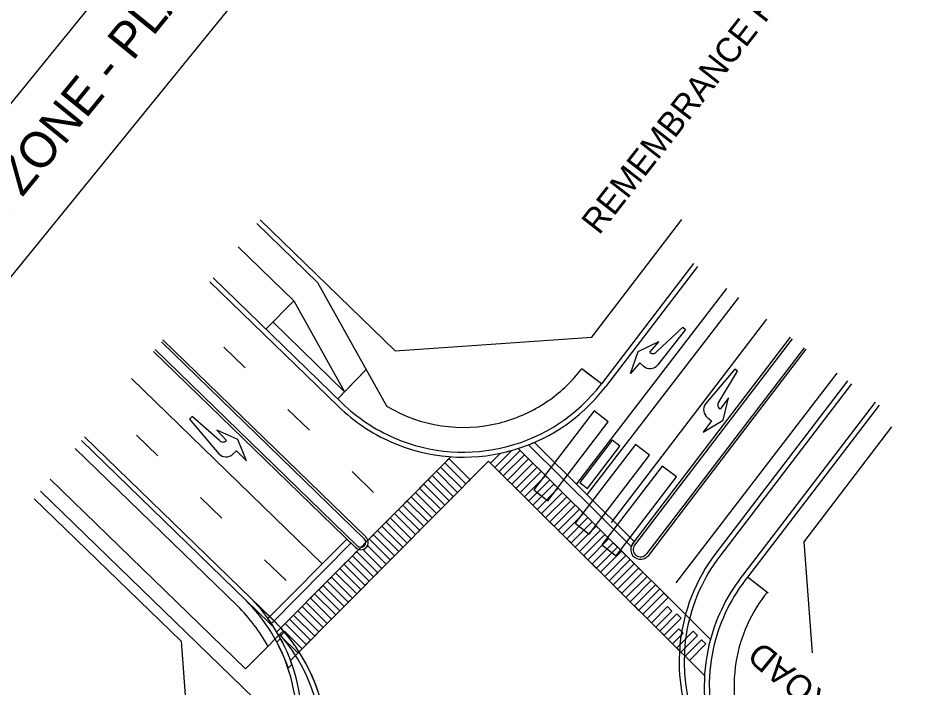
# Model space of a CAD drawing. Extents: x 592613 to 600223, y 4837996 to 4840103.
# Drawn here: x 592951.62 to 592974.48, y 4839245.35 to 4839262.21 of the extents above; entities that cross this region are included whole.
import ezdxf

# ---------------------------------------------------------------- set-up
doc = ezdxf.new("R2010")
doc.units = 0
for name, color, linetype in [('ENG_BUS-PAD', 7, 'Continuous'), ('ENG_CURB-BACK', 7, 'Continuous'), ('ENG_CURBSTOP', 7, 'Continuous'), ('ENG_EPAVT', 7, 'Continuous'), ('ENG_KILLSTRIP', 7, 'Continuous'), ('ENG_LANEWAY', 7, 'Continuous'), ('ENG_MULTI-TRAIL', 7, 'Continuous'), ('ENG_SIDEWALK', 7, 'Continuous'), ('ENG_TITLEBLOCK', 7, 'Continuous'), ('ENG_TX_TITLEBLOCK', 7, 'Continuous'), ('Level 11', 7, 'Continuous'), ('Level 12', 7, 'Continuous'), ('Level 32', 7, 'Continuous'), ('Level 33', 7, 'Continuous'), ('PMK_LANE', 7, 'Continuous'), ('PMK_LANE_3-6', 7, 'Continuous'), ('ROW_ENG_ROW', 7, 'Continuous'), ('ROW_ENG_ROW BO', 7, 'Continuous')]:
    doc.layers.add(name, color=color, linetype=linetype)

msp = doc.modelspace()

# ---------------------------------------------------------------- linework, layer by layer
at = {"layer": 'ENG_BUS-PAD'}
for p, q in [((592958.554, 4839255.093), (592957.155, 4839256.453)), ((592957.85, 4839254.383), (592958.554, 4839255.093))]:
    msp.add_line(p, q, dxfattribs=at)
at = {"layer": 'ENG_CURB-BACK'}
for p, q in [((592968.611, 4839256.033), (592966.296, 4839253.001)), ((592959.77, 4839252.518), (592956.523, 4839255.672)), ((592971.095, 4839254.137), (592968.15, 4839250.279)), ((592960.327, 4839249.101), (592955.222, 4839254.061)), ((592960.153, 4839248.921), (592955.064, 4839253.866)), ((592972.585, 4839252.999), (592969.274, 4839248.661)), ((592973.281, 4839252.468), (592969.969, 4839248.13)), ((592957.943, 4839246.973), (592953.21, 4839251.571)), ((592969.969, 4839248.13), (592969.906, 4839248.047))]:
    msp.add_line(p, q, dxfattribs=at)
for centre, radius, start, end in [((592962.819, 4839255.656), 4.375, 246.6005, 322.6377), ((592962.819, 4839255.656), 4.375, 225.8289, 246.6005), ((592960.24, 4839249.011), 0.125, 315.8289, 45.8289), ((592960.24, 4839249.011), 0.125, 225.8289, 315.8289), ((592972.751, 4839246.006), 4.375, 142.6377, 169.6205), ((592973.383, 4839245.392), 4.375, 142.6377, 167.7306), ((592954.262, 4839244.449), 4.375, 27.9119, 45.8289), ((592954.262, 4839244.449), 4.125, 28.0452, 45.829), ((592954.894, 4839243.835), 4.375, 44.5335, 45.8289), ((592954.894, 4839243.835), 4.375, 348.3699, 40.8056), ((592972.751, 4839246.006), 4.375, 169.6205, 225.8289), ((592954.262, 4839244.449), 4.375, 322.6377, 27.9119), ((592973.383, 4839245.392), 4.375, 167.7306, 225.8289)]:
    msp.add_arc(centre, radius, start, end, dxfattribs=at)
at = {"layer": 'ENG_CURBSTOP'}
msp.add_lwpolyline([(592958.411, 4839245.837), (592958.509, 4839245.936), (592958.443, 4839246.113), (592958.386, 4839246.249), (592958.331, 4839246.371), (592958.25, 4839246.534), (592958.222, 4839246.588), (592958.222, 4839246.588), (592958.131, 4839246.496), (592958.164, 4839246.417), (592958.283, 4839246.173), (592958.368, 4839245.959)], close=True, dxfattribs=at)
at = {"layer": 'ENG_EPAVT'}
for p, q in [((592968.711, 4839255.957), (592966.395, 4839252.925)), ((592959.683, 4839252.428), (592956.444, 4839255.574)), ((592971.045, 4839254.175), (592968.112, 4839250.333)), ((592960.371, 4839249.146), (592955.261, 4839254.11)), ((592971.393, 4839253.909), (592968.367, 4839249.946)), ((592960.11, 4839248.877), (592955.024, 4839253.817)), ((592971.443, 4839253.871), (592968.406, 4839249.894)), ((592972.486, 4839253.075), (592969.174, 4839248.737)), ((592973.182, 4839252.544), (592969.87, 4839248.206)), ((592958.03, 4839247.063), (592953.289, 4839251.669)), ((592957.341, 4839245.827), (592952.423, 4839250.598)), ((592968.112, 4839250.333), (592967.086, 4839248.989)), ((592968.149, 4839250.278), (592967.128, 4839248.941)), ((592968.367, 4839249.946), (592967.43, 4839248.719)), ((592968.405, 4839249.893), (592967.48, 4839248.681)), ((592969.87, 4839248.206), (592969.806, 4839248.123)), ((592957.589, 4839246.077), (592957.968, 4839246.456)), ((592957.341, 4839245.827), (592957.589, 4839246.077))]:
    msp.add_line(p, q, dxfattribs=at)
for centre, radius, start, end in [((592962.819, 4839255.656), 4.5, 246.1583, 322.6377), ((592962.819, 4839255.656), 4.5, 225.8289, 246.1583), ((592960.24, 4839249.011), 0.188, 315.8289, 45.8289), ((592960.24, 4839249.011), 0.188, 225.8289, 315.8289), ((592967.281, 4839248.832), 0.25, 141.1016, 322.9443), ((592967.281, 4839248.832), 0.187, 144.4115, 322.9443), ((592972.751, 4839246.006), 4.5, 142.6377, 174.56), ((592973.383, 4839245.392), 4.5, 142.6377, 166.783), ((592954.262, 4839244.449), 4.5, 33.0068, 45.8289), ((592954.894, 4839243.835), 4.5, 322.6377, 51.4479), ((592954.894, 4839243.835), 4.5, 349.35, 45.8289), ((592954.262, 4839244.449), 4.5, 343.3725, 33.0068), ((592972.751, 4839246.006), 4.5, 170.2582, 184.2333), ((592973.383, 4839245.392), 4.5, 166.783, 225.8289), ((592972.751, 4839246.006), 4.5, 184.2333, 225.8289)]:
    msp.add_arc(centre, radius, start, end, dxfattribs=at)
at = {"layer": 'ENG_KILLSTRIP'}
for p, q in [((592959.834, 4839252.804), (592958.026, 4839254.561)), ((592957.136, 4839247.408), (592953.052, 4839251.376))]:
    msp.add_line(p, q, dxfattribs=at)
at = {"layer": 'ENG_LANEWAY'}
for p, q in [((592969.444, 4839255.403), (592965.665, 4839250.481)), ((592969.741, 4839255.174), (592965.938, 4839250.22)), ((592972.22, 4839253.271), (592968.168, 4839247.993))]:
    msp.add_line(p, q, dxfattribs=at)
at = {"layer": 'ENG_MULTI-TRAIL'}
for p, q in [((592959.155, 4839255.555), (592957.628, 4839257.039)), ((592958.554, 4839255.093), (592959.834, 4839252.804))]:
    msp.add_line(p, q, dxfattribs=at)
at = {"layer": 'ENG_SIDEWALK'}
for p, q in [((592959.155, 4839255.555), (592960.9, 4839252.433)), ((592960.379, 4839253.366), (592959.659, 4839252.625)), ((592959.834, 4839252.804), (592960.379, 4839253.366)), ((592966.296, 4839253.001), (592965.799, 4839253.38)), ((592966.296, 4839253.001), (592965.899, 4839253.304)), ((592959.661, 4839252.623), (592959.834, 4839252.804)), ((592958.007, 4839244.645), (592952.184, 4839250.302)), ((592970.495, 4839247.729), (592969.969, 4839248.13)), ((592970.367, 4839247.827), (592969.969, 4839248.13)), ((592970.403, 4839247.668), (592970.466, 4839247.751)), ((592957.812, 4839246.298), (592958.196, 4839246.685)), ((592958.196, 4839246.685), (592958.303, 4839246.792))]:
    msp.add_line(p, q, dxfattribs=at)
for centre, start, end in [((592962.819, 4839255.656), 305.4959, 322.6377), ((592962.819, 4839255.656), 302.8741, 305.4959), ((592962.819, 4839255.656), 239.233, 283.8878), ((592962.819, 4839255.656), 283.8878, 302.8741), ((592973.383, 4839245.392), 142.6377, 172.7872), ((592973.383, 4839245.392), 172.7872, 204.683)]:
    msp.add_arc(centre, 3.75, start, end, dxfattribs=at)
at = {"layer": 'ENG_TITLEBLOCK'}
msp.add_line((592939.353, 4839240.83), (592966.893, 4839274.724), dxfattribs=at)
msp.add_line((592939.353, 4839240.83), (592966.893, 4839274.724), dxfattribs=at)
msp.add_lwpolyline([(592937.219, 4839242.565), (592964.758, 4839276.458)], dxfattribs=at)
msp.add_lwpolyline([(592937.219, 4839242.565), (592964.758, 4839276.458)], dxfattribs=at)
at = {"layer": 'Level 11'}
for p, q in [((592966.112, 4839252.318), (592964.593, 4839250.332)), ((592966.469, 4839252.045), (592966.112, 4839252.318)), ((592964.95, 4839250.059), (592966.469, 4839252.045)), ((592967.151, 4839251.478), (592965.632, 4839249.493)), ((592966.566, 4839251.58), (592965.753, 4839250.516)), ((592965.944, 4839250.37), (592966.758, 4839251.433)), ((592966.758, 4839251.433), (592966.566, 4839251.58)), ((592967.508, 4839251.205), (592967.151, 4839251.478)), ((592965.989, 4839249.219), (592967.508, 4839251.205)), ((592967.826, 4839250.932), (592966.308, 4839248.947)), ((592968.184, 4839250.659), (592967.826, 4839250.932)), ((592965.753, 4839250.516), (592965.944, 4839250.37)), ((592966.665, 4839248.673), (592968.184, 4839250.659)), ((592964.593, 4839250.332), (592964.95, 4839250.059)), ((592965.632, 4839249.493), (592965.989, 4839249.219)), ((592966.308, 4839248.947), (592966.665, 4839248.673))]:
    msp.add_line(p, q, dxfattribs=at)
at = {"layer": 'Level 12'}
for p, q in [((592967.685, 4839253.805), (592968.346, 4839254.433)), ((592968.415, 4839254.372), (592967.709, 4839253.47)), ((592968.346, 4839254.433), (592968.415, 4839254.372)), ((592967.216, 4839253.815), (592967.741, 4839254.067)), ((592967.741, 4839254.067), (592967.503, 4839253.8)), ((592967.025, 4839253.265), (592967.216, 4839253.815)), ((592967.264, 4839253.532), (592967.025, 4839253.265)), ((592967.356, 4839253.45), (592967.264, 4839253.532)), ((592969.649, 4839253.375), (592968.914, 4839252.496)), ((592969.247, 4839252.542), (592969.722, 4839253.321)), ((592969.722, 4839253.321), (592969.649, 4839253.375)), ((592969.491, 4839252.653), (592969.28, 4839252.363)), ((592969.355, 4839252.086), (592969.491, 4839252.653)), ((592955.998, 4839252.179), (592955.932, 4839252.116)), ((592955.932, 4839252.116), (592956.67, 4839251.239)), ((592956.682, 4839251.575), (592955.998, 4839252.179)), ((592968.857, 4839251.784), (592969.355, 4839252.086)), ((592969.069, 4839252.074), (592968.857, 4839251.784)), ((592968.969, 4839252.147), (592969.069, 4839252.074)), ((592957.15, 4839251.603), (592956.616, 4839251.835)), ((592956.616, 4839251.835), (592956.864, 4839251.576)), ((592957.361, 4839251.059), (592957.15, 4839251.603)), ((592957.023, 4839251.232), (592957.113, 4839251.318)), ((592957.113, 4839251.318), (592957.361, 4839251.059))]:
    msp.add_line(p, q, dxfattribs=at)
for centre, radius, start, end in [((592967.591, 4839253.888), 0.125, 228.2469, 318.2706), ((592967.523, 4839253.636), 0.25, 228.242, 318.2642), ((592969.348, 4839252.469), 0.125, 143.8443, 233.8679), ((592969.116, 4839252.349), 0.25, 143.8506, 233.8728), ((592956.772, 4839251.662), 0.125, 223.8199, 313.8436), ((592956.85, 4839251.412), 0.25, 223.8262, 313.8484)]:
    msp.add_arc(centre, radius, start, end, dxfattribs=at)
at = {"layer": 'PMK_LANE'}
for p, q in [((592970.449, 4839254.63), (592966.539, 4839249.508)), ((592959.27, 4839248.472), (592954.472, 4839253.133)), ((592964.461, 4839251.466), (592967.041, 4839248.903)), ((592964.611, 4839251.528), (592967.121, 4839249.035)), ((592962.508, 4839251.166), (592958.128, 4839246.753)), ((592963.758, 4839251.255), (592963.508, 4839251.003)), ((592963.614, 4839250.897), (592964.039, 4839251.324)), ((592964.25, 4839251.323), (592963.721, 4839250.792)), ((592963.827, 4839250.686), (592964.356, 4839251.218)), ((592964.2, 4839251.373), (592968.041, 4839247.558)), ((592964.356, 4839251.218), (592964.25, 4839251.323)), ((592963.455, 4839251.056), (592958.473, 4839246.037)), ((592962.46, 4839251.118), (592962.355, 4839251.012)), ((592962.355, 4839251.012), (592962.885, 4839250.482)), ((592962.991, 4839250.588), (592962.46, 4839251.118)), ((592963.455, 4839251.056), (592968.891, 4839245.656)), ((592963.508, 4839251.003), (592963.614, 4839250.897)), ((592964.463, 4839251.112), (592963.934, 4839250.58)), ((592964.04, 4839250.475), (592964.569, 4839251.006)), ((592964.569, 4839251.006), (592964.463, 4839251.112)), ((592962.038, 4839250.692), (592961.932, 4839250.586)), ((592962.568, 4839250.162), (592962.038, 4839250.692)), ((592962.249, 4839250.905), (592962.143, 4839250.799)), ((592962.143, 4839250.799), (592962.674, 4839250.269)), ((592962.78, 4839250.375), (592962.249, 4839250.905)), ((592963.721, 4839250.792), (592963.827, 4839250.686)), ((592964.676, 4839250.9), (592964.146, 4839250.369)), ((592964.253, 4839250.263), (592964.782, 4839250.795)), ((592964.782, 4839250.795), (592964.676, 4839250.9)), ((592961.826, 4839250.479), (592961.72, 4839250.373)), ((592962.357, 4839249.949), (592961.826, 4839250.479)), ((592961.932, 4839250.586), (592962.463, 4839250.056)), ((592962.885, 4839250.482), (592962.991, 4839250.588)), ((592963.934, 4839250.58), (592964.04, 4839250.475)), ((592964.888, 4839250.689), (592964.359, 4839250.157)), ((592964.466, 4839250.052), (592964.995, 4839250.583)), ((592965.101, 4839250.478), (592964.572, 4839249.946)), ((592964.995, 4839250.583), (592964.888, 4839250.689)), ((592965.208, 4839250.372), (592965.101, 4839250.478)), ((592961.615, 4839250.266), (592961.509, 4839250.16)), ((592962.146, 4839249.737), (592961.615, 4839250.266)), ((592961.72, 4839250.373), (592962.251, 4839249.843)), ((592962.674, 4839250.269), (592962.78, 4839250.375)), ((592964.146, 4839250.369), (592964.253, 4839250.263)), ((592964.679, 4839249.84), (592965.208, 4839250.372)), ((592965.314, 4839250.266), (592964.785, 4839249.735)), ((592965.421, 4839250.16), (592965.314, 4839250.266)), ((592961.403, 4839250.054), (592961.298, 4839249.947)), ((592961.934, 4839249.524), (592961.403, 4839250.054)), ((592961.509, 4839250.16), (592962.04, 4839249.63)), ((592962.463, 4839250.056), (592962.568, 4839250.162)), ((592964.359, 4839250.157), (592964.466, 4839250.052)), ((592964.891, 4839249.629), (592965.421, 4839250.16)), ((592965.527, 4839250.055), (592964.998, 4839249.523)), ((592965.633, 4839249.949), (592965.527, 4839250.055)), ((592961.723, 4839249.311), (592961.192, 4839249.841)), ((592961.298, 4839249.947), (592961.829, 4839249.417)), ((592962.251, 4839249.843), (592962.357, 4839249.949)), ((592964.572, 4839249.946), (592964.679, 4839249.84)), ((592965.104, 4839249.417), (592965.633, 4839249.949)), ((592965.74, 4839249.843), (592965.211, 4839249.312)), ((592965.846, 4839249.738), (592965.74, 4839249.843)), ((592960.981, 4839249.628), (592960.875, 4839249.521)), ((592961.512, 4839249.098), (592960.981, 4839249.628)), ((592961.086, 4839249.734), (592961.617, 4839249.204)), ((592962.04, 4839249.63), (592962.146, 4839249.737)), ((592964.785, 4839249.735), (592964.891, 4839249.629)), ((592965.317, 4839249.206), (592965.846, 4839249.738)), ((592965.953, 4839249.632), (592965.424, 4839249.1)), ((592966.059, 4839249.526), (592965.953, 4839249.632)), ((592960.769, 4839249.415), (592960.664, 4839249.308)), ((592961.3, 4839248.885), (592960.769, 4839249.415)), ((592960.875, 4839249.521), (592961.406, 4839248.991)), ((592961.829, 4839249.417), (592961.934, 4839249.524)), ((592964.998, 4839249.523), (592965.104, 4839249.417)), ((592965.53, 4839248.995), (592966.059, 4839249.526)), ((592966.166, 4839249.421), (592965.636, 4839248.889)), ((592966.272, 4839249.315), (592966.166, 4839249.421)), ((592959.887, 4839249.093), (592957.903, 4839247.095)), ((592960.558, 4839249.202), (592960.452, 4839249.095)), ((592960.452, 4839249.095), (592960.983, 4839248.566)), ((592961.089, 4839248.672), (592960.558, 4839249.202)), ((592960.664, 4839249.308), (592961.195, 4839248.778)), ((592961.406, 4839248.991), (592961.512, 4839249.098)), ((592961.617, 4839249.204), (592961.723, 4839249.311)), ((592965.211, 4839249.312), (592965.317, 4839249.206)), ((592965.424, 4839249.1), (592965.53, 4839248.995)), ((592965.743, 4839248.783), (592966.272, 4839249.315)), ((592966.378, 4839249.209), (592965.849, 4839248.678)), ((592965.956, 4839248.572), (592966.485, 4839249.103)), ((592966.485, 4839249.103), (592966.378, 4839249.209)), ((592959.994, 4839248.989), (592957.99, 4839246.97)), ((592960.415, 4839248.921), (592960.309, 4839248.814)), ((592960.878, 4839248.459), (592960.415, 4839248.921)), ((592961.195, 4839248.778), (592961.3, 4839248.885)), ((592965.636, 4839248.889), (592965.743, 4839248.783)), ((592966.591, 4839248.998), (592966.062, 4839248.466)), ((592966.169, 4839248.36), (592966.698, 4839248.892)), ((592966.698, 4839248.892), (592966.591, 4839248.998)), ((592960.135, 4839248.776), (592960.03, 4839248.67)), ((592960.03, 4839248.67), (592960.56, 4839248.14)), ((592960.666, 4839248.246), (592960.135, 4839248.776)), ((592960.309, 4839248.814), (592960.772, 4839248.353)), ((592960.983, 4839248.566), (592961.089, 4839248.672)), ((592965.849, 4839248.678), (592965.956, 4839248.572)), ((592966.804, 4839248.786), (592966.275, 4839248.255)), ((592966.381, 4839248.149), (592966.91, 4839248.681)), ((592966.91, 4839248.681), (592966.804, 4839248.786)), ((592959.924, 4839248.563), (592959.818, 4839248.457)), ((592959.818, 4839248.457), (592960.349, 4839247.927)), ((592960.455, 4839248.033), (592959.924, 4839248.563)), ((592960.772, 4839248.353), (592960.878, 4839248.459)), ((592966.062, 4839248.466), (592966.169, 4839248.36)), ((592967.017, 4839248.575), (592966.488, 4839248.043)), ((592966.594, 4839247.938), (592967.123, 4839248.469)), ((592967.123, 4839248.469), (592967.017, 4839248.575)), ((592959.713, 4839248.35), (592959.607, 4839248.244)), ((592959.607, 4839248.244), (592960.138, 4839247.714)), ((592960.243, 4839247.82), (592959.713, 4839248.35)), ((592960.56, 4839248.14), (592960.666, 4839248.246)), ((592966.275, 4839248.255), (592966.381, 4839248.149)), ((592967.23, 4839248.363), (592966.701, 4839247.832)), ((592966.807, 4839247.726), (592967.336, 4839248.258)), ((592967.336, 4839248.258), (592967.23, 4839248.363)), ((592959.501, 4839248.137), (592959.396, 4839248.031)), ((592959.396, 4839248.031), (592959.926, 4839247.501)), ((592960.032, 4839247.607), (592959.501, 4839248.137)), ((592960.349, 4839247.927), (592960.455, 4839248.033)), ((592966.488, 4839248.043), (592966.594, 4839247.938)), ((592967.443, 4839248.152), (592966.913, 4839247.62)), ((592967.02, 4839247.515), (592967.549, 4839248.046)), ((592967.549, 4839248.046), (592967.443, 4839248.152)), ((592959.29, 4839247.924), (592959.184, 4839247.818)), ((592959.184, 4839247.818), (592959.715, 4839247.288)), ((592959.821, 4839247.395), (592959.29, 4839247.924)), ((592960.138, 4839247.714), (592960.243, 4839247.82)), ((592966.701, 4839247.832), (592966.807, 4839247.726)), ((592967.655, 4839247.941), (592967.126, 4839247.409)), ((592967.233, 4839247.303), (592967.762, 4839247.835)), ((592967.868, 4839247.729), (592967.339, 4839247.198)), ((592967.762, 4839247.835), (592967.655, 4839247.941)), ((592967.975, 4839247.623), (592967.868, 4839247.729)), ((592958.867, 4839247.499), (592958.762, 4839247.392)), ((592959.398, 4839246.969), (592958.867, 4839247.499)), ((592959.079, 4839247.712), (592958.973, 4839247.605)), ((592958.973, 4839247.605), (592959.504, 4839247.075)), ((592959.609, 4839247.182), (592959.079, 4839247.712)), ((592959.926, 4839247.501), (592960.032, 4839247.607)), ((592966.913, 4839247.62), (592967.02, 4839247.515)), ((592967.446, 4839247.092), (592967.975, 4839247.623)), ((592968.041, 4839247.558), (592969.039, 4839246.566)), ((592958.656, 4839247.286), (592958.55, 4839247.179)), ((592959.187, 4839246.756), (592958.656, 4839247.286)), ((592958.762, 4839247.392), (592959.292, 4839246.862)), ((592959.715, 4839247.288), (592959.821, 4839247.395)), ((592967.126, 4839247.409), (592967.233, 4839247.303)), ((592967.956, 4839247.392), (592967.552, 4839246.986)), ((592967.666, 4839246.873), (592968.07, 4839247.279)), ((592968.07, 4839247.279), (592967.956, 4839247.392)), ((592958.445, 4839247.073), (592958.339, 4839246.966)), ((592958.975, 4839246.543), (592958.445, 4839247.073)), ((592958.55, 4839247.179), (592959.081, 4839246.649)), ((592959.504, 4839247.075), (592959.609, 4839247.182)), ((592967.339, 4839247.198), (592967.446, 4839247.092)), ((592968.197, 4839247.209), (592967.765, 4839246.775)), ((592967.871, 4839246.669), (592968.303, 4839247.103)), ((592968.303, 4839247.103), (592968.197, 4839247.209)), ((592958.339, 4839246.966), (592958.87, 4839246.436)), ((592959.292, 4839246.862), (592959.398, 4839246.969)), ((592967.552, 4839246.986), (592967.666, 4839246.873)), ((592968.242, 4839246.829), (592967.978, 4839246.563)), ((592968.349, 4839246.723), (592968.242, 4839246.829)), ((592958.329, 4839246.765), (592958.223, 4839246.658)), ((592958.223, 4839246.658), (592958.658, 4839246.224)), ((592958.764, 4839246.33), (592958.329, 4839246.765)), ((592959.081, 4839246.649), (592959.187, 4839246.756)), ((592967.765, 4839246.775), (592967.871, 4839246.669)), ((592968.084, 4839246.458), (592968.349, 4839246.723)), ((592968.607, 4839246.77), (592968.191, 4839246.352)), ((592968.297, 4839246.246), (592968.714, 4839246.665)), ((592968.714, 4839246.665), (592968.607, 4839246.77)), ((592958.87, 4839246.436), (592958.975, 4839246.543)), ((592967.978, 4839246.563), (592968.084, 4839246.458)), ((592968.191, 4839246.352), (592968.297, 4839246.246)), ((592968.817, 4839246.556), (592968.403, 4839246.141)), ((592968.51, 4839246.035), (592968.923, 4839246.45)), ((592968.923, 4839246.45), (592968.817, 4839246.556)), ((592958.658, 4839246.224), (592958.764, 4839246.33)), ((592968.403, 4839246.141), (592968.51, 4839246.035))]:
    msp.add_line(p, q, dxfattribs=at)
for points in [[(592964.461, 4839251.466), (592964.611, 4839251.528), (592967.121, 4839249.035), (592967.041, 4839248.903)], [(592957.903, 4839247.095), (592959.887, 4839249.093), (592959.994, 4839248.989), (592957.99, 4839246.97)]]:
    msp.add_lwpolyline(points, close=True, dxfattribs=at)
for points in [[(592963.975, 4839251.307), (592963.975, 4839251.305), (592963.904, 4839251.288)], [(592961.192, 4839249.841), (592961.098, 4839249.746), (592961.086, 4839249.734)]]:
    msp.add_lwpolyline(points, dxfattribs=at)
for start, end in [(282.0553, 283.9602), (284.8874, 285.7389)]:
    msp.add_arc((592962.819, 4839255.656), 4.5, start, end, dxfattribs=at)
at = {"layer": 'PMK_LANE_3-6'}
for p, q in [((592957.332, 4839253.404), (592956.794, 4839253.927)), ((592958.946, 4839251.837), (592958.408, 4839252.359)), ((592955.131, 4839251.187), (592954.593, 4839251.709)), ((592960.56, 4839250.269), (592960.022, 4839250.791)), ((592956.745, 4839249.619), (592956.207, 4839250.141)), ((592958.359, 4839248.051), (592957.821, 4839248.573))]:
    msp.add_line(p, q, dxfattribs=at)
at = {"layer": 'ROW_ENG_ROW'}
for p, q in [((592961.108, 4839253.832), (592957.707, 4839257.136)), ((592961.108, 4839253.832), (592966.057, 4839254.18)), ((592955.721, 4839246.518), (592952.026, 4839250.107)), ((592971.605, 4839246.23), (592971.398, 4839249.026)), ((592955.721, 4839246.518), (592956.135, 4839240.926))]:
    msp.add_line(p, q, dxfattribs=at)
at = {"layer": 'ROW_ENG_ROW BO'}
for p, q in [((592966.057, 4839254.18), (592968.317, 4839257.139)), ((592971.398, 4839249.026), (592973.606, 4839251.918))]:
    msp.add_line(p, q, dxfattribs=at)

# ---------------------------------------------------------------- texts
at = {"layer": 'ENG_TX_TITLEBLOCK'}
msp.add_text('DETECTION ZONE - PLAN VIEW', height=0.9, rotation=50.9062, dxfattribs=at).set_placement((592947.124, 4839252.03))
at = {"layer": 'Level 32'}
msp.add_text('CREDITVIEW ROAD', height=0.625, rotation=140.5921, dxfattribs=at).set_placement((592976.415, 4839241.537))
at = {"layer": 'Level 33'}
msp.add_text('REMEMBRANCE ROAD', height=0.61958, rotation=52.007, dxfattribs=at).set_placement((592966.237, 4839256.731))

doc.saveas('drawing.dxf')
